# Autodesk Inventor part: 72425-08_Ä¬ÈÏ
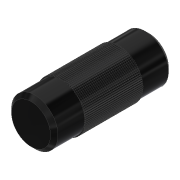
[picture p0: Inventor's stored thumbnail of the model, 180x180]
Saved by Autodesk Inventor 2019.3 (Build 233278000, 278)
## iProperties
Created: 2010-06
Part Number: 72425-08_Ä¬ÈÏ
Material: Ogólny
Document SubType Name: Modeling
Designer: CADENGINEERING4
Density: 1 g/cm^3
Appearance: Gładki — czarny
Author: CADENGINEERING4
Revision Number: ÈÎºÎ
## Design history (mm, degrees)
feature "NONE"
node "Bryła1"
